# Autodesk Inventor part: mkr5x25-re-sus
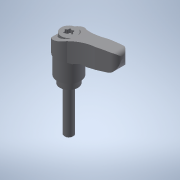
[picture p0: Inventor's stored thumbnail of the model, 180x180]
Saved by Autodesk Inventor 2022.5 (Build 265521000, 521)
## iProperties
Created: 2017-09
Part Number: mkr5x25-re-sus
Material: 一般
Document SubType Name: Modeling
Designer: imaocorp
Density: 1 g/cm^3
Appearance: 既定
Author: imaocorp
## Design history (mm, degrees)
node "mkr5x25-re-sus.x_t1"
node "mkr5x25-re-sus"
node "Base1"
